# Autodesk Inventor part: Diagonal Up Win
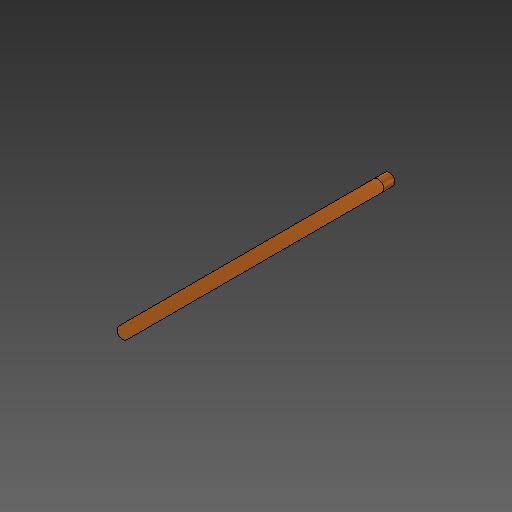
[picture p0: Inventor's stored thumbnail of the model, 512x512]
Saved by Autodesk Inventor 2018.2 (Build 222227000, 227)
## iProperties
Created: 2018-03
Part Number: Diagonal Up Win
Material: Gold
Document SubType Name: Modeling
Designer: PeterMaxwell-Stewart
Mass: 79.0948 g
Surface Area: 33.1781 cm^2
Volume: 4.09817 cm^3
Density: 19.3 g/cm^3
Appearance: Metal 1600F Hot
Author: PeterMaxwell-Stewart
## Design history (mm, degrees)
derived "O's and X's.ipt"
feature "Diagonal Up Win::O's and X's.ipt" dims "d0" = 10
tag "TaggingFeature1"
body "Solid1"
